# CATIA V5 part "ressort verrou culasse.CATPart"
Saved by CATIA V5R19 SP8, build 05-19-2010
Part number: ressort verrou culasse
Bounding box of the stored display mesh (mm): x 0 to 2.5, y 0 to 17, z 0 to 5.641
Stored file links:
  C:\Users\Arthur\Desktop\Catia parts\GLOCK\Poignée\ressort verrou culasse.CATPart
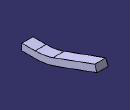
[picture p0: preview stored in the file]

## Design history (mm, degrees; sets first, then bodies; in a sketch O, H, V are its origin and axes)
Set1
  Sketch1 on yz-plane, origin (0, 0, 0), H (0, 1, 0), V (0, 0, 1)
    line L1 (0, 0) -> (3, 0)
    line L2 (3, 1.5) -> (0, 1.5)
    line L3 (0, 1.5) -> (0, 0)
    point P1 (5.3731, 0)
    point P2 (5.1086, 1.5)
    point P4 (5.3731, 0)
    line L4 (7.6031, 0.8116) -> (17, 4.2318)
    line L5 (17, 4.2318) -> (16.487, 5.6414)
    line L6 (16.487, 5.6414) -> (7.09, 2.2212)
    point P5 (17, 4.2318)
    point P7 (5.1086, 1.5)
    arc A1 centre (3, 13.4585) radius 13.4585 from (7.6031, 0.8116) to (3, 0) cw
    arc A2 centre (3, 13.4585) radius 11.9585 from (7.09, 2.2212) to (3, 1.5) cw
    distance P5 L3 = 17
    length L3 = 1.5
    length L5 = 1.5
    angle L3 L5 = 20
    length L6 = 10
    length L4 = 10
    length L2 = 3
    horizontal: L1 H, L2 H
    vertical: L3 V
    perpendicularity: L5 L6, L4 L5
    coincidence: P4 P1, P7 P2, L4 P4, L1 P1, L6 P7, L2 P2
    tangency: A1 L4, A1 L1, A2 L6, A2 L2
Body1 (main body)
  Pad1: profile Sketch1, direction (1, 0, 0), length 2.5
